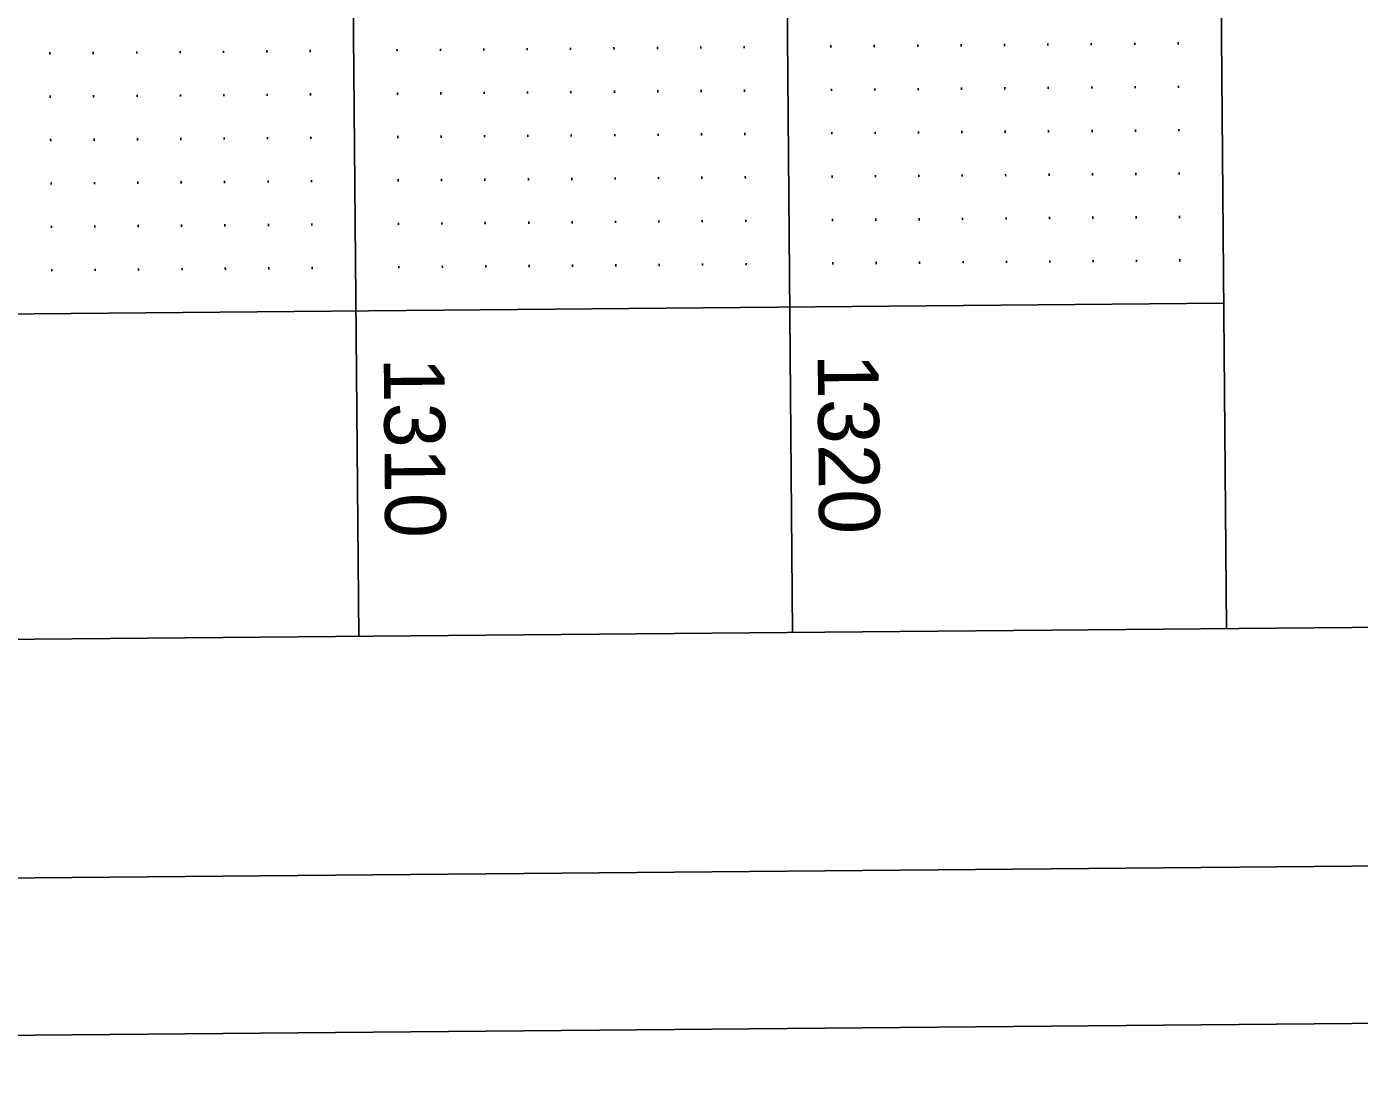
# Model space of a CAD drawing. Extents: x 2149873 to 2152007, y 140538 to 142349.
# Drawn here: x 2150351.2 to 2150504.8, y 140538.2 to 140658.5 of the extents above; entities that cross this region are included whole.
import ezdxf

# ---------------------------------------------------------------- set-up
doc = ezdxf.new("R2010")
doc.units = 0
for name, color, linetype in [('SHT_Plan_Profile_Sheet_Elev_Txt', 7, 'Continuous'), ('SHT_Plot_Shape_Full', 7, 'Continuous'), ('SHT_Plot_Shape_Half', 7, 'Continuous'), ('SHT_Profile_Grid_Major', 7, 'Continuous'), ('SHT_Profile_Grid_Minor', 7, 'Continuous'), ('SHT_Sheet_Border', 7, 'Continuous')]:
    doc.layers.add(name, color=color, linetype=linetype)

msp = doc.modelspace()

# ---------------------------------------------------------------- linework, layer by layer
at = {"layer": 'SHT_Plot_Shape_Full'}
msp.add_lwpolyline([(2151072.86, 142348.62), (2151088.62, 140548.69), (2149888.66, 140538.18), (2149872.91, 142338.11)], close=True, dxfattribs=at)
at = {"layer": 'SHT_Plot_Shape_Half'}
msp.add_lwpolyline([(2151032.33, 142266.38), (2151047.21, 140566.45), (2149947.25, 140556.82), (2149932.37, 142256.76)], close=True, dxfattribs=at)
at = {"layer": 'SHT_Profile_Grid_Major'}
for p, q in [((2150425.71, 142163.57), (2150439.49, 140588.63)), ((2150375.71, 142163.13), (2150389.5, 140588.19))]:
    msp.add_line(p, q, dxfattribs=at)
at = {"layer": 'SHT_Profile_Grid_Minor'}
for p, q in [((2150353.91, 140655.51), (2150353.91, 140655.26)), ((2150358.91, 140655.55), (2150358.91, 140655.3)), ((2150363.91, 140655.6), (2150363.91, 140655.35)), ((2150368.91, 140655.64), (2150368.91, 140655.39)), ((2150373.91, 140655.68), (2150373.91, 140655.43)), ((2150378.9, 140655.73), (2150378.91, 140655.48)), ((2150383.9, 140655.77), (2150383.91, 140655.52)), ((2150393.9, 140655.86), (2150393.91, 140655.61)), ((2150398.9, 140655.9), (2150398.91, 140655.65)), ((2150403.9, 140655.95), (2150403.91, 140655.7)), ((2150408.9, 140655.99), (2150408.91, 140655.74)), ((2150413.9, 140656.03), (2150413.91, 140655.78)), ((2150418.9, 140656.08), (2150418.91, 140655.83)), ((2150423.9, 140656.12), (2150423.91, 140655.87)), ((2150428.9, 140656.17), (2150428.91, 140655.92)), ((2150433.9, 140656.21), (2150433.91, 140655.96)), ((2150443.9, 140656.3), (2150443.9, 140656.05)), ((2150448.9, 140656.34), (2150448.9, 140656.09)), ((2150453.9, 140656.38), (2150453.9, 140656.13)), ((2150458.9, 140656.43), (2150458.9, 140656.18)), ((2150463.9, 140656.47), (2150463.9, 140656.22)), ((2150468.9, 140656.52), (2150468.9, 140656.27)), ((2150473.9, 140656.56), (2150473.9, 140656.31)), ((2150478.9, 140656.6), (2150478.9, 140656.35)), ((2150483.9, 140656.65), (2150483.9, 140656.4)), ((2150368.95, 140650.64), (2150368.95, 140650.39)), ((2150373.95, 140650.68), (2150373.95, 140650.43)), ((2150378.95, 140650.73), (2150378.95, 140650.48)), ((2150383.95, 140650.77), (2150383.95, 140650.52)), ((2150393.95, 140650.86), (2150393.95, 140650.61)), ((2150398.95, 140650.9), (2150398.95, 140650.65)), ((2150403.95, 140650.95), (2150403.95, 140650.7)), ((2150408.95, 140650.99), (2150408.95, 140650.74)), ((2150413.95, 140651.03), (2150413.95, 140650.78)), ((2150418.95, 140651.08), (2150418.95, 140650.83)), ((2150423.95, 140651.12), (2150423.95, 140650.87)), ((2150428.95, 140651.17), (2150428.95, 140650.92)), ((2150433.95, 140651.21), (2150433.95, 140650.96)), ((2150443.95, 140651.3), (2150443.95, 140651.05)), ((2150448.95, 140651.34), (2150448.95, 140651.09)), ((2150453.95, 140651.38), (2150453.95, 140651.13)), ((2150458.95, 140651.43), (2150458.95, 140651.18)), ((2150463.95, 140651.47), (2150463.95, 140651.22)), ((2150468.95, 140651.52), (2150468.95, 140651.27)), ((2150473.95, 140651.56), (2150473.95, 140651.31)), ((2150478.94, 140651.6), (2150478.95, 140651.35)), ((2150483.94, 140651.65), (2150483.95, 140651.4)), ((2150353.95, 140650.51), (2150353.95, 140650.26)), ((2150358.95, 140650.55), (2150358.95, 140650.3)), ((2150363.95, 140650.6), (2150363.95, 140650.35)), ((2150413.99, 140646.03), (2150413.99, 140645.78)), ((2150418.99, 140646.08), (2150418.99, 140645.83)), ((2150423.99, 140646.12), (2150423.99, 140645.87)), ((2150428.99, 140646.17), (2150428.99, 140645.92)), ((2150433.99, 140646.21), (2150433.99, 140645.96)), ((2150443.99, 140646.3), (2150443.99, 140646.05)), ((2150448.99, 140646.34), (2150448.99, 140646.09)), ((2150453.99, 140646.38), (2150453.99, 140646.13)), ((2150458.99, 140646.43), (2150458.99, 140646.18)), ((2150463.99, 140646.47), (2150463.99, 140646.22)), ((2150468.99, 140646.52), (2150468.99, 140646.27)), ((2150473.99, 140646.56), (2150473.99, 140646.31)), ((2150478.99, 140646.6), (2150478.99, 140646.35)), ((2150483.99, 140646.65), (2150483.99, 140646.4)), ((2150353.99, 140645.51), (2150354, 140645.26)), ((2150358.99, 140645.55), (2150359, 140645.3)), ((2150363.99, 140645.6), (2150364, 140645.35)), ((2150368.99, 140645.64), (2150369, 140645.39)), ((2150373.99, 140645.68), (2150373.99, 140645.43)), ((2150378.99, 140645.73), (2150378.99, 140645.48)), ((2150383.99, 140645.77), (2150383.99, 140645.52)), ((2150393.99, 140645.86), (2150393.99, 140645.61)), ((2150398.99, 140645.9), (2150398.99, 140645.65)), ((2150403.99, 140645.95), (2150403.99, 140645.7)), ((2150408.99, 140645.99), (2150408.99, 140645.74)), ((2150459.03, 140641.43), (2150459.04, 140641.18)), ((2150464.03, 140641.47), (2150464.04, 140641.22)), ((2150469.03, 140641.52), (2150469.04, 140641.27)), ((2150474.03, 140641.56), (2150474.03, 140641.31)), ((2150479.03, 140641.6), (2150479.03, 140641.35)), ((2150484.03, 140641.65), (2150484.03, 140641.4)), ((2150354.04, 140640.51), (2150354.04, 140640.26)), ((2150359.04, 140640.55), (2150359.04, 140640.3)), ((2150364.04, 140640.6), (2150364.04, 140640.35)), ((2150369.04, 140640.64), (2150369.04, 140640.39)), ((2150374.04, 140640.68), (2150374.04, 140640.43)), ((2150379.04, 140640.73), (2150379.04, 140640.48)), ((2150384.04, 140640.77), (2150384.04, 140640.52)), ((2150394.04, 140640.86), (2150394.04, 140640.61)), ((2150399.04, 140640.9), (2150399.04, 140640.65)), ((2150404.04, 140640.95), (2150404.04, 140640.7)), ((2150409.04, 140640.99), (2150409.04, 140640.74)), ((2150414.03, 140641.03), (2150414.04, 140640.78)), ((2150419.03, 140641.08), (2150419.04, 140640.83)), ((2150424.03, 140641.12), (2150424.04, 140640.87)), ((2150429.03, 140641.17), (2150429.04, 140640.92)), ((2150434.03, 140641.21), (2150434.04, 140640.96)), ((2150444.03, 140641.3), (2150444.04, 140641.05)), ((2150449.03, 140641.34), (2150449.04, 140641.09)), ((2150454.03, 140641.38), (2150454.04, 140641.13)), ((2150354.08, 140635.51), (2150354.08, 140635.26)), ((2150359.08, 140635.55), (2150359.08, 140635.3)), ((2150364.08, 140635.6), (2150364.08, 140635.35)), ((2150369.08, 140635.64), (2150369.08, 140635.39)), ((2150374.08, 140635.68), (2150374.08, 140635.43)), ((2150379.08, 140635.73), (2150379.08, 140635.48)), ((2150384.08, 140635.77), (2150384.08, 140635.52)), ((2150394.08, 140635.86), (2150394.08, 140635.61)), ((2150399.08, 140635.9), (2150399.08, 140635.65)), ((2150404.08, 140635.95), (2150404.08, 140635.7)), ((2150409.08, 140635.99), (2150409.08, 140635.74)), ((2150414.08, 140636.03), (2150414.08, 140635.78)), ((2150419.08, 140636.08), (2150419.08, 140635.83)), ((2150424.08, 140636.12), (2150424.08, 140635.87)), ((2150429.08, 140636.17), (2150429.08, 140635.92)), ((2150434.08, 140636.21), (2150434.08, 140635.96)), ((2150444.08, 140636.3), (2150444.08, 140636.05)), ((2150449.08, 140636.34), (2150449.08, 140636.09)), ((2150454.08, 140636.38), (2150454.08, 140636.13)), ((2150459.08, 140636.43), (2150459.08, 140636.18)), ((2150464.08, 140636.47), (2150464.08, 140636.22)), ((2150469.08, 140636.52), (2150469.08, 140636.27)), ((2150474.08, 140636.56), (2150474.08, 140636.31)), ((2150479.08, 140636.6), (2150479.08, 140636.35)), ((2150484.08, 140636.65), (2150484.08, 140636.4)), ((2150369.12, 140630.64), (2150369.13, 140630.39)), ((2150374.12, 140630.68), (2150374.13, 140630.43)), ((2150379.12, 140630.73), (2150379.13, 140630.48)), ((2150384.12, 140630.77), (2150384.13, 140630.52)), ((2150394.12, 140630.86), (2150394.13, 140630.61)), ((2150399.12, 140630.9), (2150399.13, 140630.65)), ((2150404.12, 140630.95), (2150404.13, 140630.7)), ((2150409.12, 140630.99), (2150409.12, 140630.74)), ((2150414.12, 140631.03), (2150414.12, 140630.78)), ((2150419.12, 140631.08), (2150419.12, 140630.83)), ((2150424.12, 140631.12), (2150424.12, 140630.87)), ((2150429.12, 140631.17), (2150429.12, 140630.92)), ((2150434.12, 140631.21), (2150434.12, 140630.96)), ((2150444.12, 140631.3), (2150444.12, 140631.05)), ((2150449.12, 140631.34), (2150449.12, 140631.09)), ((2150454.12, 140631.39), (2150454.12, 140631.14)), ((2150459.12, 140631.43), (2150459.12, 140631.18)), ((2150464.12, 140631.47), (2150464.12, 140631.22)), ((2150469.12, 140631.52), (2150469.12, 140631.27)), ((2150474.12, 140631.56), (2150474.12, 140631.31)), ((2150479.12, 140631.6), (2150479.12, 140631.35)), ((2150484.12, 140631.65), (2150484.12, 140631.4)), ((2150354.12, 140630.51), (2150354.13, 140630.26)), ((2150359.12, 140630.55), (2150359.13, 140630.3)), ((2150364.12, 140630.6), (2150364.13, 140630.35))]:
    msp.add_line(p, q, dxfattribs=at)
at = {"layer": 'SHT_Sheet_Border'}
for p, q in [((2150475.71, 142164.01), (2150489.49, 140589.07)), ((2150014.18, 140622.41), (2150489.16, 140626.57))]:
    msp.add_line(p, q, dxfattribs=at)
msp.add_lwpolyline([(2151008.19, 142168.67), (2151021.97, 140593.73), (2149972.01, 140584.54), (2149958.23, 142159.48)], close=True, dxfattribs=at)

# ---------------------------------------------------------------- texts
at = {"layer": 'SHT_Plan_Profile_Sheet_Elev_Txt'}
for s, p in [('1320', (2150442.37, 140620.76)), ('1310', (2150392.37, 140620.32))]:
    msp.add_text(s, height=7, rotation=270.5015, dxfattribs=at).set_placement(p)

doc.saveas('drawing.dxf')
